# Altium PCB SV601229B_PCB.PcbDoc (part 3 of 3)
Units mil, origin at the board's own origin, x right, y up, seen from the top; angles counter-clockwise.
Board outline 3875 x 2375 mil, 10 copper layers (Top Layer, MidLayer1, MidLayer2, MidLayer3, MidLayer4, MidLayer5, MidLayer6, MidLayer7, MidLayer8, Bottom Layer), stack 98 mil thick; 184 components, 75 nets, 694 pads, 496 vias.
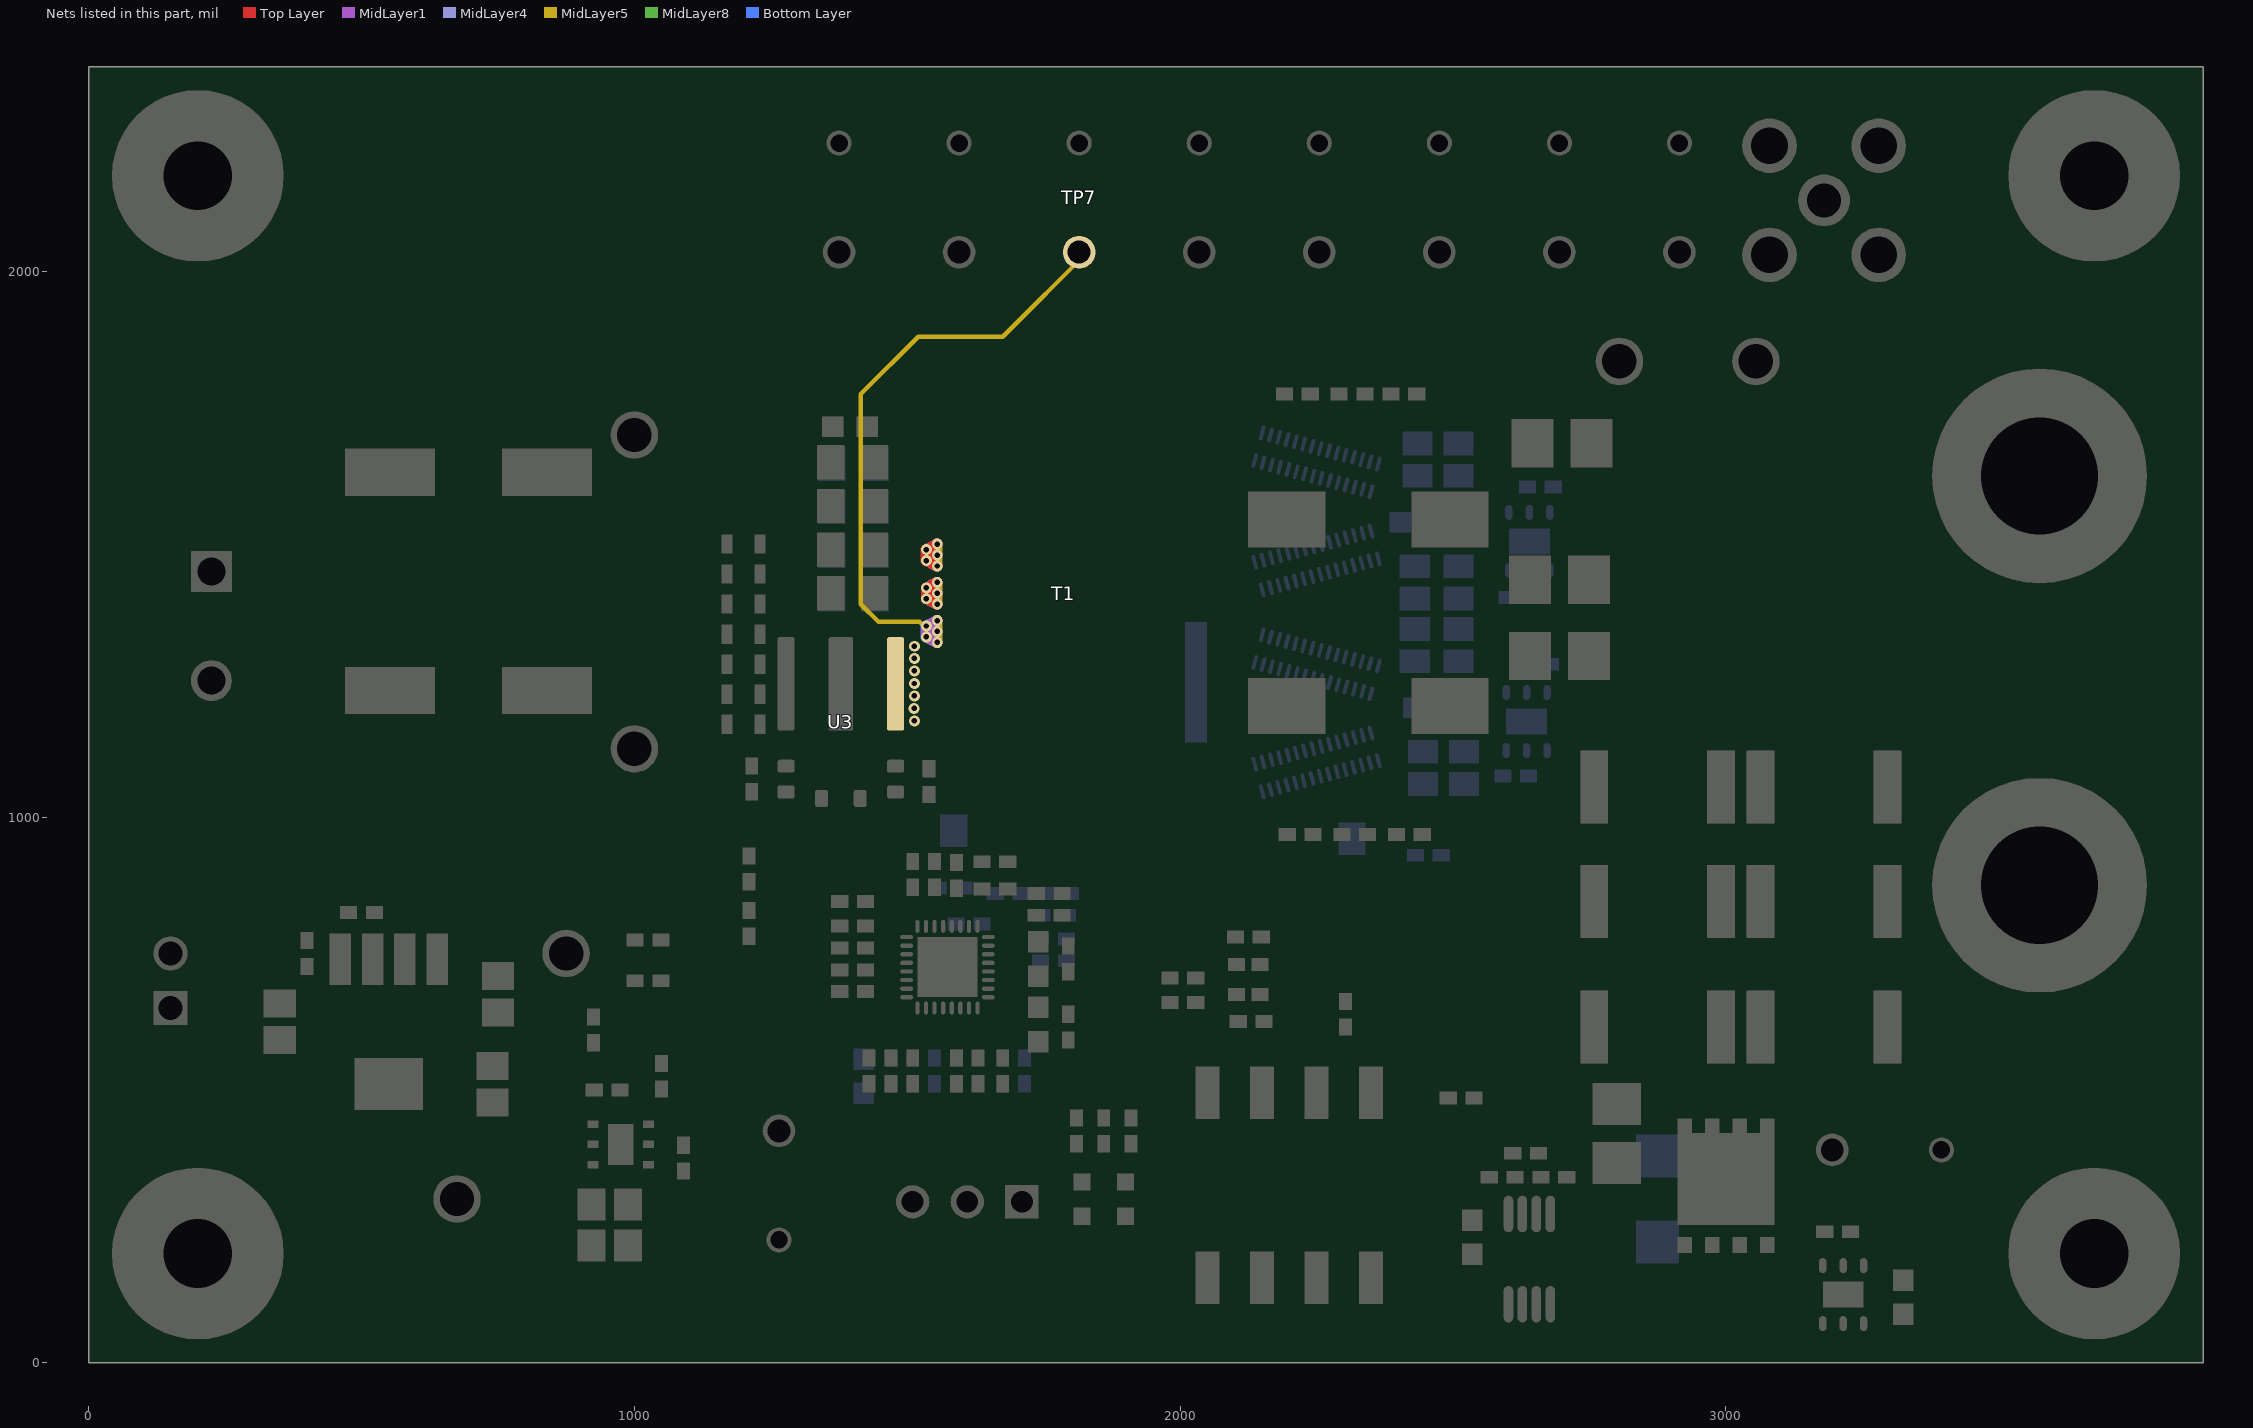
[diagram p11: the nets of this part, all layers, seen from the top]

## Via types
v1: diameter 20, hole 10, Top Layer to Bottom Layer, tented both sides, 459 vias
v2: diameter 20, hole 10, Top Layer to Bottom Layer, 29 vias
v3: diameter 19.68, hole 7.87, Top Layer to Bottom Layer, 8 vias

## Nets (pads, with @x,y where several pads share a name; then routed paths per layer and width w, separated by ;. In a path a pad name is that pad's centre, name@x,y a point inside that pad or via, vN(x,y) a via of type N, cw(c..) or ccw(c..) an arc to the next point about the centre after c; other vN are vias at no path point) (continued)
VPRI_SW: T1.1 TP7.1 U3.8 | length 4010.5
  Top Layer w20: v1@1554.64,1460 1546.64,1464 v1@1534.64,1470 ; v1@1554.64,1480 1546.64,1476 1542.64,1474 v1@1534.64,1470 ; v1@1554.64,1500 1546.64,1496 1534.64,1490 v1@1534.64,1470 ; v1(1555,1390) 1547,1394 v1(1535,1400) ; v1(1555,1410) 1547,1406 1543,1404 v1(1535,1400) ; v1(1555,1430) 1547,1426 v1(1535,1420) v1(1535,1400)
  MidLayer1 w20: v1(1555,1320) 1547,1324 v1(1535,1330) ; v1(1555,1340) 1547,1336 1543,1334 v1(1535,1330) ; v1(1555,1360) 1547,1356 v1(1535,1350) v1(1535,1330) ; v1(1555,1390) 1547,1394 v1(1535,1400) ; v1(1555,1410) 1547,1406 1543,1404 v1(1535,1400) ; v1(1555,1430) 1547,1426 v1(1535,1420) v1(1535,1400) ; v1(1555,1460) 1547,1464 v1(1535,1470) ; v1(1555,1480) 1547,1476 1543,1474 v1(1535,1470) ; v1(1555,1500) 1547,1496 v1(1535,1490) v1(1535,1470)
  MidLayer4 w20: v1(1555,1320) 1547,1324 v1(1535,1330) ; v1(1555,1340) 1547,1336 1543,1334 v1(1535,1330) ; v1(1555,1360) 1547,1356 v1(1535,1350) v1(1535,1330) ; v1(1555,1390) 1547,1394 v1(1535,1400) ; v1(1555,1410) 1547,1406 1543,1404 v1(1535,1400) ; v1(1555,1430) 1547,1426 v1(1535,1420) v1(1535,1400) ; v1(1555,1460) 1547,1464 v1(1535,1470) ; v1(1555,1480) 1547,1476 1543,1474 v1(1535,1470) ; v1(1555,1500) 1547,1496 v1(1535,1490) v1(1535,1470)
  MidLayer5 w8: v1@1530.1,1350 1522.35,1357.75 1447.25,1357.75 1415,1390 1415,1775 1520,1880 1675,1880 TP7.1@1835,2040
  MidLayer5 w20: v1(1535,1330) v1@1543,1334 ; v1(1535,1330) v1(1535,1350) ; v1(1535,1330) v1(1535,1350) ; v1(1535,1330) v1(1535,1350) ; v1(1535,1330) v1(1535,1350) ; v1(1535,1330) v1@1547,1324 ; v1(1535,1330) v1@1547,1324 ; v1(1535,1330) v1@1547,1324 ; v1(1535,1330) v1@1547,1324 ; v1(1535,1330) v1@1543,1334 ; v1(1535,1330) v1@1547,1324 ; v1(1535,1330) v1(1535,1350) ; v1(1535,1350) v1@1543,1346 ; v1(1535,1350) v1@1547,1356 ; v1(1535,1350) v1@1547,1356 ; v1(1535,1350) v1@1547,1356 ; v1(1535,1350) v1@1547,1356 ; v1(1535,1350) v1@1547,1356 ; v1(1535,1350) v1@1543,1346 ; v1(1535,1400) v1(1535,1420) ; v1(1535,1400) v1(1535,1420) ; v1(1535,1400) v1(1535,1420) ; v1(1535,1400) v1(1535,1420) ; v1(1535,1400) v1@1543,1404 ; v1(1535,1400) v1@1547,1394 ; v1(1535,1400) v1@1547,1394 ; v1(1535,1400) v1@1547,1394 ; v1(1535,1400) v1@1543,1404 ; v1(1535,1400) v1@1543,1404 ; v1(1535,1400) v1@1547,1394 ; v1(1535,1400) v1@1547,1394 ; v1(1535,1400) v1(1535,1420) ; v1(1535,1400) v1@1543,1404 ; v1(1535,1400) v1@1547,1394 ; v1(1535,1400) v1(1535,1420) ; v1(1535,1420) v1@1547,1426 ; v1(1535,1420) v1@1547,1426 ; v1(1535,1420) v1@1547,1426 ; v1(1535,1420) v1@1547,1426 ; v1(1535,1420) v1@1547,1426 ; v1(1535,1420) v1@1547,1426 ; v1(1535,1420) 1543,1416 1547,1414 v1(1555,1410) ; v1(1535,1470) v1@1547,1464 ; v1(1535,1470) v1@1543,1474 ; v1(1535,1470) v1@1543,1474 ; v1(1535,1470) v1(1535,1490) ; v1(1535,1470) v1(1535,1490) ; v1(1535,1470) v1(1535,1490) ; v1(1535,1470) v1@1543,1474 ; v1(1535,1470) v1@1543,1474 ; v1(1535,1470) v1@1543,1474 ; v1(1535,1470) v1(1535,1490) ; v1(1535,1470) v1(1535,1490) ; v1(1535,1470) v1(1535,1490) ; v1(1535,1470) v1@1547,1464 ; v1(1535,1470) v1@1547,1464 ; v1(1535,1470) v1@1547,1464 ; v1(1535,1470) v1@1547,1464 ; v1(1535,1470) v1@1547,1464 ; v1(1535,1470) v1@1543,1474 ; v1(1535,1470) v1@1547,1464 ; v1(1535,1470) v1(1535,1490) ; v1(1535,1490) v1@1547,1496 ; v1(1535,1490) v1@1547,1496 ; v1(1535,1490) v1@1547,1496 ; v1(1535,1490) v1@1547,1496 ; v1(1535,1490) v1@1547,1496 ; v1(1535,1490) v1@1547,1496 ; v1(1535,1490) v1@1547,1496 ; v1(1535,1490) 1543,1486 1547,1484 v1(1555,1480) ; v1@1543,1334 v1@1547,1336 ; v1@1543,1334 v1@1547,1336 ; v1@1543,1346 v1@1547,1344 ; v1@1543,1346 v1@1547,1344 ; v1@1543,1404 v1@1547,1406 ; v1@1543,1404 v1@1547,1406 ; v1@1543,1404 v1@1547,1406 ; v1@1543,1404 v1@1547,1406 ; v1@1543,1474 v1@1547,1476 ; v1@1543,1474 v1@1547,1476 ; v1@1543,1474 v1@1547,1476 ; v1@1543,1474 v1@1547,1476 ; v1@1543,1474 v1@1547,1476 ; v1@1543,1474 v1@1547,1476 ; v1@1547,1324 v1(1555,1320) ; v1@1547,1324 v1(1555,1320) ; v1@1547,1324 v1(1555,1320) ; v1@1547,1324 v1(1555,1320) ; v1@1547,1336 v1(1555,1340) ; v1@1547,1336 v1(1555,1340) ; v1@1547,1344 v1(1555,1340) ; v1@1547,1344 v1(1555,1340) ; v1@1547,1356 v1(1555,1360) ; v1@1547,1356 v1(1555,1360) ; v1@1547,1356 v1(1555,1360) ; v1@1547,1356 v1(1555,1360) ; v1@1547,1356 v1(1555,1360) ; v1@1547,1394 v1(1555,1390) ; v1@1547,1394 v1(1555,1390) ; v1@1547,1394 v1(1555,1390) ; v1@1547,1394 v1(1555,1390) ; v1@1547,1394 v1(1555,1390) ; v1@1547,1394 v1(1555,1390) ; v1@1547,1406 v1(1555,1410) ; v1@1547,1406 v1(1555,1410) ; v1@1547,1406 v1(1555,1410) ; v1@1547,1406 v1(1555,1410) ; v1@1547,1426 v1(1555,1430) ; v1@1547,1426 v1(1555,1430) ; v1@1547,1426 v1(1555,1430) ; v1@1547,1426 v1(1555,1430) ; v1@1547,1426 v1(1555,1430) ; v1@1547,1426 v1(1555,1430) ; v1@1547,1464 v1(1555,1460) ; v1@1547,1464 v1(1555,1460) ; v1@1547,1464 v1(1555,1460) ; v1@1547,1464 v1(1555,1460) ; v1@1547,1464 v1(1555,1460) ; v1@1547,1464 v1(1555,1460) ; v1@1547,1464 v1(1555,1460) ; v1@1547,1476 v1(1555,1480) ; v1@1547,1476 v1(1555,1480) ; v1@1547,1476 v1(1555,1480) ; v1@1547,1476 v1(1555,1480) ; v1@1547,1476 v1(1555,1480) ; v1@1547,1476 v1(1555,1480) ; v1@1547,1496 v1(1555,1500) ; v1@1547,1496 v1(1555,1500) ; v1@1547,1496 v1(1555,1500) ; v1@1547,1496 v1(1555,1500) ; v1@1547,1496 v1(1555,1500) ; v1@1547,1496 v1(1555,1500) ; v1@1547,1496 v1(1555,1500) ; v1(1555,1320) v1(1555,1340) ; v1(1555,1320) v1(1555,1340) ; v1(1555,1340) v1(1555,1360) ; v1(1555,1340) v1(1555,1360) ; v1(1555,1390) v1(1555,1410) ; v1(1555,1390) v1(1555,1410) ; v1(1555,1410) v1(1555,1430) ; v1(1555,1410) v1(1555,1430) ; v1(1555,1460) v1(1555,1480) ; v1(1555,1460) v1(1555,1480) ; v1(1555,1480) v1(1555,1500) ; v1(1555,1480) v1(1555,1500)
  MidLayer8 w20: v1(1555,1320) 1547,1324 v1(1535,1330) ; v1(1555,1340) 1547,1336 1543,1334 v1(1535,1330) ; v1(1555,1360) 1547,1356 v1(1535,1350) v1(1535,1330) ; v1(1555,1390) 1547,1394 v1(1535,1400) ; v1(1555,1410) 1547,1406 1543,1404 v1(1535,1400) ; v1(1555,1430) 1547,1426 v1(1535,1420) v1(1535,1400) ; v1(1555,1460) 1547,1464 v1(1535,1470) ; v1(1555,1480) 1547,1476 1543,1474 v1(1535,1470) ; v1(1555,1500) 1547,1496 v1(1535,1490) v1(1535,1470)
  Bottom Layer w20: v1@1543,1403 v1@1547,1405 ; v1@1547,1405.96 v1(1555,1410) ; v1@1554,1319.82 1546,1323.82 v1@1534,1329.82 ; v1@1554,1339.82 1546,1335.82 1542,1333.82 v1@1534,1329.82 ; v1@1554,1359.82 1546,1355.82 1534,1349.82 v1@1534,1329.82 ; v1(1555,1390) 1547,1393.96 v1(1535,1400) v1(1535,1420) 1547,1425.96 v1(1555,1430) ; v1(1555,1460) 1547,1464 v1(1535,1470) ; v1(1555,1480) 1547,1476 1543,1474 v1(1535,1470) ; v1(1555,1500) 1547,1496 v1(1535,1490) v1(1535,1470)
  other v1: 1513,1176 1512.73,1199 1513,1222 1513,1244.68 1513,1267.76 1513,1290.73 1513,1313
pads on no net: H1.1 H2.1 H3.1 H4.1 LBL1.0 Q2. Q3. Q4. Q5. U1.2 U2.5 U3.1A U3.1B U3.1C U3.1D U3.1E U3.8A U3.8B U3.8C U3.8D U3.8E U3.9A U3.9B U3.9C U3.9D U3.9E U4.4 U4.22 U4.30 U4.32 U5.5

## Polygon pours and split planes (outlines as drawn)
VPRI_SW on Top Layer "VPRI_SW_L01_P182" (solid, remove dead copper, pour order 182): 44 vertices, not listed, extent 1535,1050.26 2132.4,1722.27
VPRI_SW on Top Layer "VPRI_SW_L01_P180" (solid, remove dead copper, pour order 180): 1541.07,1306.07 1565.54,1306.07 1565.54,1370.42 1566.22,1371.1 1505.41,1371.1 1494.1,1359.79 1462.47,1359.79 1462.47,1320.61 1463.62,1319.45 1463.62,1157.89 1515.47,1157.89 1525.73,1168.15 1525.73,1290.73
VOUT on Top Layer "Top Layer-No Net 14" (solid, remove dead copper, pour order 155): 2890,1755 3140,1755 3300,1915 3705,1915 3850,1770 3850,1360 3625,1135 2725,1135 2710,1120 2710,1045 2695,1030 2520,1030 2400,1150 2400,1585 2570,1755
SEC_D1 on Top Layer "Top Layer-No Net 16" (solid, remove dead copper, pour order 142): 2015,1395 2095,1395 2150,1450 2310,1450 2350,1490 2350,1560 2340,1570 2255,1570 2210,1615 2015,1615 2010,1610 2010,1400 2015,1395
SPGND on Top Layer "Top Layer-No Net 13" (solid, remove dead copper, pour order 132): 2850,25 3020,25 3055,60 3055,225 3045,235 2910,235 2860,285 2860,390 2840,410 2730,410 2675,355 2675,200
DR4 on Top Layer "Top Layer-No Net 12" (solid, remove dead copper, pour order 131): 3185,725 3310,725 3350,685 3350,495 3105,250 2910,250 2900,260 2900,440 3002.5,542.5 3162.5,542.5 3170,550 3170,710
V3P3_CTRL on Top Layer "Top Layer-No Net 10" (solid, remove dead copper, pour order 108): 930,220 945,220 960,235 960,345 930,375 880,375 865,360 865,235 880,220
V5_CTRL on Top Layer "Top Layer-No Net 8" (solid, remove dead copper, pour order 106): 905,600 1055,600 1090,565 1090,430 1060,400 920,400 885,435 885,580 905,600
V5 on Top Layer "Top Layer-No Net 7" (solid, remove dead copper, pour order 94): 885,610 955,610 1025,680 1025,835 970,890 875,890 830,845 830,645 865,610
VBIAS_IN on Top Layer "Top Layer-No Net 5" (solid, remove dead copper, pour order 91): 80,940 730,940 810,860 810,700 790,680 450,680 400,630 300,630 220,710 70,710 20,760 20,880
VPRI_CAP on Top Layer "Top Layer-No Net" (solid, remove dead copper, pour order 121): 1495,1375 1505,1385 1505,1715 1485,1735 1435,1735 1405,1705 1405,1385 1415,1375
VBUS_P on Top Layer "Top Layer-No Net 3" (solid, remove dead copper, pour order 125): 1230,1135 1270,1135 1295,1160 1295,1345 1325,1375 1385,1375 1390,1380 1390,1735 1385,1740 1270,1740 1220,1690 1220,1145
VBUS_N on Top Layer "Top Layer-No Net 1" (solid, remove dead copper, pour order 124): 1425,1160 1425,1330 1415,1340 1345,1340 1335,1330 1335,1165 1345,1155 1420,1155 1425,1160
VOUT on Top Layer "Top Layer-No Net 4" (solid, remove dead copper, pour order 126): 2430,1645 2430,1125 2470,1085 2550,1085 2575,1110 2575,1630 2555,1650 2450,1650 2430,1630
VBUS_N on Top Layer "Top Layer-No Net 2" (solid, remove dead copper, pour order 127): 1160,1520 1180,1520 1185,1515 1185,1145 1175,1135 1135,1135 1130,1140 1130,1510 1140,1520
VBUS_P on Top Layer "Top Layer-No Net 9" (solid, remove dead copper, pour order 97): 105,1750 1375,1750 1385,1740 1385,1565 1335,1515 1230,1515 1205,1540 1125,1540 1095,1510 1095,1290 855,1050 480,1050 50,1480 50,1695
SEC_D2 on Top Layer "Top Layer-No Net 15" (solid, remove dead copper, pour order 137): 2035,1105 2050,1090 2080,1090 2195,1090 2275,1170 2350,1170 2360,1180 2360,1235 2340,1255 2200,1255 2100,1355 2035,1355
VOUT on Top Layer "Top Layer-No Net 17" (solid, remove dead copper, pour order 156): 2605,425 2835,425 2870,460 2870,705 2855,720 2725,720 2705,740 2705,860 2685,880 2550,880 2520,850 2520,645 2590,575 2590,440 2605,425
SPGND on Top Layer "Top Layer-No Net 18" (solid, remove dead copper, pour order 163): 2715,1635 2815,1635 2835,1655 2835,1715 2820,1730 2715,1730
SPGND on Top Layer "Top Layer-No Net 19" (solid, remove dead copper, pour order 165): 2710,1390 2815,1390 2830,1405 2830,1465 2810,1485 2710,1485
SPGND on Top Layer "Top Layer-No Net 19" (solid, remove dead copper, pour order 164): 2710,1250 2815,1250 2830,1265 2830,1325 2810,1345 2710,1345
SPGND on Top Layer "Top Layer-No Net 20" (solid, remove dead copper, pour order 166): 2715,1250 2815,1250 2830,1265 2830,1325 2810,1345 2710,1345 2710,1250
AGND on Top Layer "Top Layer-No Net 21" (solid, remove dead copper, pour order 178): 23 vertices, not listed, extent 31.54,0 2646.54,970
SEC_D1 on MidLayer1 "SEC_D1_L02_P209" (solid, remove dead copper, pour order 209): 26 vertices, not listed, extent 1538,1063.19 2097,1692
SEC_D2 on MidLayer1 "Top Layer-No Net 15" (solid, remove dead copper, pour order 195): 2041,1099 2050,1090 2080,1090 2195,1090 2230,1125 2320,1125 2360,1165 2360,1235 2340,1255 2200,1255 2100,1355 2041,1355
SEC_D1 on MidLayer1 "Top Layer-No Net 16" (solid, remove dead copper, pour order 193): 2015,1395 2095,1395 2150,1450 2310,1450 2350,1490 2350,1560 2340,1570 2295,1615 2015,1615 2010,1610 2010,1400
AGND on MidLayer1 "MidLayer1-No Net" (solid, remove dead copper, pour order 90): 80,940 2520,940 2605,855 2605,515 2740,380 3350,380 3440,290 3440,80 3380,20 80,20 20,80 20,880
VBUS_N on MidLayer1 "MidLayer1-No Net 1" (solid, remove dead copper, pour order 103): 95,1050 1090,1050 1185,1145 1410,1145 1425,1160 1425,1705 1380,1750 106.45,1750 50,1693.55 50,1095 95,1050
VOUT on MidLayer1 "Top Layer-No Net 14" (solid, remove dead copper, pour order 154): 2890,1755 3140,1755 3300,1915 3705,1915 3850,1770 3850,1360 3625,1135 3420,1135 3315,1030 2520,1030 2400,1150 2400,1585 2570,1755
VOUT on MidLayer1 "MidLayer1-No Net 2" (solid, remove dead copper, pour order 173): 2600,1045 2650,995 2650,530 2760,420 3130,420 3270,420 3360,510 3360,1140 3310,1190 2710,1190 2600,1080
VPRI_SW on Bottom Layer "VPRI_SW_L10_P223" (solid, remove dead copper, pour order 223): 1540.66,1305.97 1565.13,1305.97 1565.13,1370.32 1565.81,1371 1505,1371 1493.69,1359.69 1462.06,1359.69 1462.06,1320.5 1463.21,1319.35 1463.21,1157.79 1515.06,1157.79 1525.32,1168.05 1525.32,1290.62
SEC_D1 on Bottom Layer "SEC_D1_L10_P219" (solid, remove dead copper, pour order 219): 26 vertices, not listed, extent 1537.96,1063.4 2096.96,1692.21
SPGND on Bottom Layer "Bottom Layer-No Net 15" (solid, pour order 147): 2400,1085 2400,1105 2390,1115 2375,1115 2365,1105 2365,1095 2375,1085
VOUT on Bottom Layer "Bottom Layer-No Net 14" (solid, remove dead copper, pour order 146): 2565,1240 2565,1285 2550,1300 2405,1300 2400,1295 2400,1250 2415,1235 2560,1235
VOUT on Bottom Layer "Bottom Layer-No Net 13" (solid, remove dead copper, pour order 145): 2550,1575 2560,1585 2560,1590 2560,1630 2545,1645 2410,1645 2400,1635 2400,1585 2410,1575
VOUT on Bottom Layer "Bottom Layer-No Net 12" (solid, remove dead copper, pour order 144): 2545,1440 2560,1455 2560,1485 2560,1500 2550,1510 2410,1510 2400,1500 2400,1450 2410,1440
SPGND on Bottom Layer "Bottom Layer-No Net 4" (solid, remove dead copper, pour order 105): 2135,1025 2200,1090 2420,1090 2435,1075 2435,1010 2410,985 2150,985 2135,1000
SEC_D2 on Bottom Layer "Bottom Layer-No Net" (solid, remove dead copper, pour order 100): 2044.31,1355 2120,1279.31 2245.69,1279.31 2285,1240 2332.28,1240 2362.28,1210 2362.28,1156.41 2330.87,1125 2297.46,1125 2272.46,1100 2044.31,1100
VBUS_N on Bottom Layer "Bottom Layer-No Net 3" (solid, remove dead copper, pour order 123): 1145,1135 1400,1135 1425,1160 1425,1320 1405,1340 1405,1675 1400,1680 1275,1680 1130,1535 1130,1150
VPRI_CAP on Bottom Layer "Bottom Layer-No Net 2" (solid, remove dead copper, pour order 122): 1492.75,1680 1494.04,1681.3 1511.36,1681.3 1510,1512.73 1510,1385 1500,1375 1415,1375 1410,1380 1410,1675 1415,1680
VBUS_N on Bottom Layer "MidLayer1-No Net 1" (solid, remove dead copper, pour order 102): 95,1050 1090,1050 1185,1145 1410,1145 1425,1160 1425,1705 1380,1750 106.45,1750 50,1693.55 50,1095 95,1050
SPGND on Bottom Layer "Bottom Layer-No Net 6" (solid, remove dead copper, pour order 93): 2415,1090 2550,1090 2560,1080 2560,1005 2540,985 2405,985 2400,990 2400,1075 2415,1090
VOUT on Bottom Layer "Bottom Layer-No Net 7" (solid, remove dead copper, pour order 96): 2450,1100 2550,1100 2560,1110 2560,1165 2555,1170 2550,1175 2420,1175 2405,1160 2405,1115 2420,1100
SPGND on Bottom Layer "Bottom Layer-No Net 8" (solid, remove dead copper, pour order 99): 25 vertices, not listed, extent 2115,1270 2555,1480
SEC_D1 on Bottom Layer "Bottom Layer-No Net 9" (solid, remove dead copper, pour order 101): 18 vertices, not listed, extent 2015,1395 2365,1675
SPGND on Bottom Layer "Bottom Layer-No Net 10" (solid, remove dead copper, pour order 104): 2145,1700 2170,1675 2240,1675 2245,1675 2280,1640 2365,1640 2385,1660 2385,1725 2360,1750 2275,1750 2140,1750 2130,1740 2130,1715 2145,1700
SPGND on Bottom Layer "Bottom Layer-No Net 11" (solid, remove dead copper, pour order 107): 2370,1665 2380,1655 2550,1655 2560,1665 2560,1740 2550,1750 2360,1750 2350,1740 2350,1685
DR4 on Bottom Layer "Bottom Layer-No Net 5" (solid, remove dead copper, pour order 157): 3185,725 3310,725 3350,685 3350,525 3115,290 2870,290 2830,330 2830,435 2930,535 3165,535 3180,550 3180,720 3185,725
SPGND on Bottom Layer "Bottom Layer-No Net 16" (solid, remove dead copper, pour order 158): 2805,90 3045,90 3075,120 3075,240 3045,270 2820,270 2785,235 2785,110 2805,90
VOUT on Bottom Layer "Bottom Layer-No Net 17" (solid, remove dead copper, pour order 159): 2670,475 2825,475 2870,520 2870,705 2855,720 2610,720 2585,695 2585,500 2610,475
SPGND on Bottom Layer "Bottom Layer-No Net 18" (solid, remove dead copper, pour order 160): 41 vertices, not listed, extent 2480,590 3850,1920
PGND on Bottom Layer "Bottom Layer-No Net 19" (solid, remove dead copper, pour order 168): 1610,1000 1610,1080 1580,1110 1505,1110 1500,1105 1500,1075 1505,1070 1550,1070 1560,1060 1560,1000
AGND on Bottom Layer "Bottom Layer-No Net 20" (solid, remove dead copper, pour order 169): 18 vertices, not listed, extent 20,25 2755,955
SEC_D1 on MidLayer6 "SEC_D1_L07_P215" (solid, remove dead copper, pour order 215): 26 vertices, not listed, extent 1538,1063.19 2097,1692
SEC_D1 on MidLayer6 "Top Layer-No Net 16" (solid, remove dead copper, pour order 141): 2015,1395 2095,1395 2150,1450 2310,1450 2350,1490 2350,1560 2340,1570 2295,1615 2015,1615 2010,1610 2010,1400
SEC_D2 on MidLayer6 "Top Layer-No Net 15" (solid, remove dead copper, pour order 136): 2043,1097 2050,1090 2080,1090 2195,1090 2230,1125 2320,1125 2360,1165 2360,1235 2340,1255 2200,1255 2096,1359 2043,1359
SPGND on MidLayer6 "MidLayer4-No Net 2" (solid, remove dead copper, pour order 152): 41 vertices, not listed, extent 2100,25 3850,1880
AGND on MidLayer6 "MidLayer6-No Net" (solid, remove dead copper, pour order 177): 105,940 2545,940 2670,815 2670,180 2515,25 80,25 20,85 20,880 80,940
VPRI_SW on MidLayer4 "VPRI_SW_L05_P186" (solid, remove dead copper, pour order 186): 28 vertices, not listed, extent 1535,1064.41 2103.35,1696.3
SEC_D1 on MidLayer4 "Top Layer-No Net 16" (solid, remove dead copper, pour order 140): 2015,1395 2095,1395 2150,1450 2310,1450 2350,1490 2350,1560 2340,1570 2295,1615 2015,1615 2010,1610 2010,1400
SEC_D2 on MidLayer4 "Top Layer-No Net 15" (solid, remove dead copper, pour order 135): 2035,1105 2050,1090 2080,1090 2195,1090 2230,1125 2320,1125 2355,1160 2355,1195 2345,1205 2345,1250 2340,1255 2200,1255 2100,1355 2035,1355
VBUS_P on MidLayer4 "Top Layer-No Net 9" (solid, remove dead copper, pour order 95): 105,1750 1375,1750 1385,1740 1385,1565 1335,1515 1230,1515 1205,1540 1125,1540 1095,1510 1095,1340 805,1050 480,1050 50,1480 50,1695 105,1750
SPGND on MidLayer4 "MidLayer4-No Net 2" (solid, remove dead copper, pour order 151): 41 vertices, not listed, extent 2100,25 3850,1880
SEC_D1 on MidLayer3 "SEC_D1_L04_P213" (solid, remove dead copper, pour order 213): 26 vertices, not listed, extent 1538,1063.19 2097,1692
SEC_D2 on MidLayer3 "Top Layer-No Net 15" (solid, remove dead copper, pour order 201): 2040.65,1099 2049.65,1090 2079.65,1090 2194.65,1090 2229.65,1125 2319.65,1125 2359.65,1165 2359.65,1235 2339.65,1255 2199.65,1255 2099.65,1355 2040.65,1355
SEC_D1 on MidLayer3 "Top Layer-No Net 16" (solid, remove dead copper, pour order 139): 2015,1395 2095,1395 2150,1450 2310,1450 2350,1490 2350,1560 2340,1570 2295,1615 2015,1615 2010,1610 2010,1400
CTRL_VREF on MidLayer3 "MidLayer3-No Net 1" (solid, remove dead copper, pour order 133): 1720,430 1840,550 1840,850 1735,955 1445,955 1255,765 1255,615 1440,430
SPGND on MidLayer3 "MidLayer4-No Net 2" (solid, remove dead copper, pour order 150): 41 vertices, not listed, extent 2100,25 3850,1880
V5_LM5200 on MidLayer3 "MidLayer3-No Net" (solid, remove dead copper, pour order 170): 18 vertices, not listed, extent 1035,735 1565,1110
SEC_D1 on MidLayer2 "SEC_D1_L03_P211" (solid, remove dead copper, pour order 211): 26 vertices, not listed, extent 1538,1063.19 2097,1692
SEC_D1 on MidLayer2 "Top Layer-No Net 16" (solid, remove dead copper, pour order 199): 2015,1395 2095,1395 2150,1450 2310,1450 2350,1490 2350,1560 2340,1570 2295,1615 2015,1615 2010,1610 2010,1400
SEC_D2 on MidLayer2 "Top Layer-No Net 15" (solid, remove dead copper, pour order 197): 2041,1099 2050,1090 2080,1090 2195,1090 2230,1125 2320,1125 2360,1165 2360,1235 2340,1255 2200,1255 2100,1355 2041,1355
V5_CTRL on MidLayer2 "MidLayer2-No Net 2" (solid, remove dead copper, pour order 111): 905,610 1135,610 1455,930 1540,930 1615,855 2585,855 2695,745 2695,610 2635,550 2020,550 1830,360 1050,360 875,535 875,580
V5 on MidLayer2 "MidLayer2-No Net" (solid, remove dead copper, pour order 92): 500,940 815,940 860,895 860,520 1035,345 1855,345 2035,525 3315,525 3440,400 3440,80 3380,20 590,20 360,250 360,800
V5_GD on MidLayer2 "MidLayer2-No Net 1" (solid, remove dead copper, pour order 167): 21 vertices, not listed, extent 1000,620 2700,1575
SEC_D1 on MidLayer5 "SEC_D1_L06_P221" (solid, remove dead copper, pour order 221): 26 vertices, not listed, extent 1537.96,1063.4 2096.96,1692.21
SEC_D1 on MidLayer5 "Top Layer-No Net 16" (solid, remove dead copper, pour order 203): 2015,1395 2095,1395 2150,1450 2310,1450 2350,1490 2350,1560 2340,1570 2295,1615 2015,1615 2010,1610 2010,1400
SEC_D2 on MidLayer5 "Top Layer-No Net 15" (solid, remove dead copper, pour order 134): 2041,1099 2050,1090 2080,1090 2195,1090 2230,1125 2320,1125 2360,1165 2360,1235 2340,1255 2200,1255 2100,1355 2041,1355
VBUS_N on MidLayer5 "MidLayer1-No Net 1" (solid, remove dead copper, pour order 98): 95,1050 1090,1050 1185,1145 1410,1145 1425,1160 1425,1705 1380,1750 106.45,1750 50,1693.55 50,1095 95,1050
VOUT on MidLayer5 "Top Layer-No Net 14" (solid, remove dead copper, pour order 153): 2890,1755 3140,1755 3300,1915 3705,1915 3850,1770 3850,1360 3625,1135 3420,1135 3315,1030 2520,1030 2400,1150 2400,1585 2570,1755
VOUT on MidLayer5 "MidLayer5-No Net" (solid, remove dead copper, pour order 172): 2510,1090 2510,630 2645,495 2870,495 2895,520 3035,520 3315,800 3315,1090 3265,1140 2560,1140
SEC_D1 on MidLayer7 "SEC_D1_L08_P217" (solid, remove dead copper, pour order 217): 26 vertices, not listed, extent 1538,1063.19 2097,1692
SEC_D2 on MidLayer7 "Top Layer-No Net 15" (solid, remove dead copper, pour order 207): 2044,1096 2050,1090 2080,1090 2195,1090 2230,1125 2320,1125 2360,1165 2360,1235 2340,1255 2200,1255 2096,1359 2044,1359
SEC_D1 on MidLayer7 "Top Layer-No Net 16" (solid, remove dead copper, pour order 205): 2015,1395 2095,1395 2150,1450 2310,1450 2350,1490 2350,1560 2340,1570 2295,1615 2015,1615 2010,1610 2010,1400
V3P3_CTRL on MidLayer7 "MidLayer7-No Net" (solid, remove dead copper, pour order 138): 1020,20 2135,20 2190,75 2190,535 1855,870 1275,870 835,430 835,190 1005,20
PGND on MidLayer7 "MidLayer7-No Net 1" (solid, remove dead copper, pour order 171): 1315,2300 1800,2300 1870,2230 1870,1940 1730,1800 1485,1800 1390,1705 1390,1240 1530,1100 1530,1005 1470,945 820,945 720,1045 720,1925 1095,2300
SPGND on MidLayer7 "MidLayer7-No Net 2" (solid, remove dead copper, pour order 174): 2150,955 2505,955 2560,1010 2560,1065 2540,1085 2160,1085 2125,1050 2125,980
SPGND on MidLayer7 "MidLayer7-No Net 3" (solid, remove dead copper, pour order 175): 2250,1280 2320,1280 2360,1320 2385,1320 2420,1285 2550,1285 2570,1305 2570,1415 2530,1455 2335,1455 2315,1435 2155,1435 2120,1400 2120,1360 2200,1280
SPGND on MidLayer7 "MidLayer7-No Net 4" (solid, remove dead copper, pour order 176): 2145,1635 2330,1635 2380,1685 2525,1685 2540,1700 2540,1740 2520,1760 2130,1760 2100,1730 2100,1680
VPRI_SW on MidLayer8 "VPRI_SW_L09_P191" (solid, remove dead copper, pour order 191): 32 vertices, not listed, extent 1547,1060 2093,1687.52
SPGND on MidLayer8 "MidLayer4-No Net" (solid, remove dead copper, pour order 148): 2370,1085 2585,1085 2670,1170 2670,1195 2580,1285 2450,1285 2415,1320 2370,1320 2350,1300 2350,1220 2350,1215 2365,1200 2365,1090 2370,1085
SPGND on MidLayer8 "MidLayer4-No Net 1" (solid, remove dead copper, pour order 149): 2380,1460 2640,1460 2680,1500 2680,1535 2535,1680 2375,1680 2350,1655 2350,1575 2365,1560 2365,1475 2380,1460
VPRI_CAP on MidLayer8 "MidLayer8-No Net 1" (solid, remove dead copper, pour order 143): 1524,1524 1495,1495 1485,1495 1480,1500 1480,1540 1480,1635 1490,1645 1505,1645 1524,1626
VPRI_CAP on MidLayer8 "MidLayer8-No Net 2" (solid, remove dead copper, pour order 120): 1485,1375 1500,1375 1515,1390 1515,1670 1505,1680 1460,1680 1455,1675 1455,1385 1465,1375
VBUS_P on MidLayer8 "MidLayer8-No Net" (solid, remove dead copper, pour order 110): 105,1750 1379.31,1750 1406.81,1722.5 1406.81,1381.81 1395,1370 1125,1370 805,1050 95,1050 50,1095 50,1695 50.49,1695.49
SPGND on MidLayer8 "MidLayer8-No Net 3" (solid, remove dead copper, pour order 161): 44 vertices, not listed, extent 2105,390 3845,1915
SPGND on MidLayer8 "MidLayer8-No Net 4" (solid, remove dead copper, pour order 162): 3465,1910 3465,2180 3310,2335 2035,2335 1930,2230 1930,1950 2115,1765 2635,1765 2765,1895 2780,1895 3450,1895

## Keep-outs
Keep-Out Layer:
  the board outline again, w10
  text ".Layer_Name" at 577,-858.49 h60

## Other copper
Top Layer:
  rectangle net SPGND: 3275,130 3345,175
  rectangle net V5: 3250,55 3285,85
  rectangle net V5: 3275,55 3345,110
  rectangle net AGND: 955,465 1000,515
  rectangle net AGND: 701.9,425 778.1,505
  rectangle net AGND: 465,440 620,560
  rectangle net AGND: 305,535 390,620
  rectangle net V5: 700,520 780,600
  rectangle net V5: 500,780 510,800
  rectangle net V5: 510,740 540,840
  rectangle net SEC_D2: 2124.76,1245 2255,1265
  rectangle net SEC_D1: 2125,1480 2255,1505
  rectangle net VBUS_N: 755,1185 925,1305
  rectangle net VBUS_N: 755,1560 925,1675
  rectangle net NetR34_1: 2890,955 3165,1125
  rectangle net NetR35_2: 2890,550 3020,945
  rectangle net NetR34_2: 2725,735 2880,1125
  rectangle net NetR37_1: 3175,735 3350,1125
  rectangle net NetR38_1: 3030,550 3165,945
  rectangle net AGND: 695,615 810,670
  rectangle net V3P3_CTRL: 875,210 940,345
  rectangle net AGND: 965,175 1045,335
  text ".Layer_Name" at 577,-858.49 h60
MidLayer8:
  rectangle net VPRI_CAP: 1474,1375 1510,1615
  rectangle net VPRI_CAP: 1475.65,1615 1510,1650
Bottom Layer:
  rectangle net NetR46_2: 2890,550 3020,945
  rectangle net NetR43_1: 3030,550 3165,945
  rectangle net NetR42_1: 3175,735 3350,1125
  rectangle net NetR42_2: 2890,955 3165,1125
  rectangle net NetR45_2: 2725,735 2880,1125
  rectangle net PGND: 1560,995 1600,1020
  rectangle net PGND: 1525,1070 1565,1110
  rectangle net AGND: 1550,930 1625,955
  rectangle net AGND: 2275,920 2355,955
  text ".Layer_Name" at 577,-858.49 h60

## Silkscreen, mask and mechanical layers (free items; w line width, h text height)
Top Overlay:
  rectangle: 1945,120 2000,175
  rectangle: 1065,50 1395,175
  lines w4: 1708.52,888.6 1730,915 ; 1715,395 1720,390 1770,390 1775,395 ; 1715,925 1730,945 ; 1750,390 1780,360 1895,360 1900,355 ; 1815,360 1820,360 1825,355 ; 2730,310 2730,300 2740,290
  text "V_OUT" at 2845,2000 h40 r90
  text "PWM_H" at 1315,1995 h40 r90
  text "PWM_L" at 1535,1995 h40 r90
  text "SW_NODE" at 1755,1995 h40 r90
  text "SEC_D1" at 1975,1995 h40 r90
  text "SEC_D2" at 2195,1995 h40 r90
  text "SR_G2" at 2415,1995 h40 r90
  text "SR_G1" at 2635,1995 h40 r90
  text "LMG5200 GaN 48V-PoL EVM" at 75,1925 h55
  text "Hot Surface" at 1795,1855 h65
  text "LMG5200POLEVM-10" at 75,1825 h55
  text "Input Volt" at 50,1725 h50
  text "-VOUT+" at 2825,1715 h40
  text "36-75 VDC" at 50,1650 h40
  text "+" at 50,1575 h60
  text "VBUS+" at 925,1575 h40
  text "+" at 3395,1360 h80
  text "Output Voltage" at 3195,1275 h50
  text "0.5-1.5 VDC/50 A" at 3215,1195 h40
  text "-" at 3390,1085 h80
  text "-" at 50,1075 h60
  text "Danger:" at 375,1000 h70
  text "VBUS-" at 925,1000 h40
  text "High Voltage" at 375,900 h70
  text "+" at 50,850 h60
  text "5V" at 750,805 h40
  text "-" at 50,525 h60
  text "Bias Voltage" at 35,475 h40
  text "Idyn" at 3270,445 h40
  text "6V-9V DC" at 50,400 h40
  text "IMON" at 1195,305 h40 r90
  text "AGND" at 585,165 h40
  text "EN" at 1920,135 h40 r90
  text "SCL" at 1535,120 h40 r90
  text "SDA" at 1630,120 h40 r90
  text "GND" at 1735,120 h40 r90
  text "SV601229-'.PCB_Rev'-" at 400,75 h60
  text "EN" at 2050,50 h40
  text "DynLoad" at 2200,50 h40
  text "I2C" at 1565,45 h40
  text "PGOOD" at 1840,30 h40 r90
  text ".Layer_Name" at 577,-858.49 h60
Bottom Overlay:
  text "RoHS Exempt" at 3160,60 h60
  text ".Layer_Name" at 577,-858.49 h60
Top Paste:
  text ".Layer_Name" at 577,-858.49 h60
Bottom Paste:
  text ".Layer_Name" at 577,-858.49 h60
Top Solder:
  text ".Layer_Name" at 577,-858.49 h60
  text ".Layer_Name" at 577,-858.49 h60
Bottom Solder:
  text ".Layer_Name" at 577,-858.49 h60
Drill Guide:
  text ".Layer_Name" at 577,-858.49 h60
M1 Board Outline:
  the board outline again, w10
  text ".Layer_Name" at 577,-858.49 h60
M2 Board Dimensions:
  rectangle: 0,-285.5 125,-160.5
  rectangle: 125,-410.5 500,-285.5
  lines w7: 0,-285.5 1000,-285.5 ; 125,-410.5 125,-160.5 ; 250,-410.5 250,-160.5 ; 500,-410.5 500,-160.5 ; 750,-410.5 750,-160.5 ; 0,-410.5 1000,-410.5 1000,-160.5 0,-160.5 0,-410.5
  text ".Layer_Name" at 577,-858.49 h60
M3 3D STEP Top:
  text ".Layer_Name" at 577,-858.49 h60
M4 3D STEP Bottom:
  text ".Layer_Name" at 577,-858.49 h60
M5 Assembly Top:
  lines w4: 1875,1710 2990,3180
  lines w10: -292,-930.17 6308,-930.17 ; -292,-726.83 6310,-726.83 ; -292,-523.5 -292,-1133.5 3713,-1133.5 6310,-1133.5 6310,-523.5 -291.5,-523.5 -291.5,-1133.5 1284,-1133.5 ; 2173,-1133.5 2173,-523.5 ; 3440,-726.83 3440,-523.5 ; 4280,-726.83 4280,-523.5 ; 4902,-1140 4902,-937.17
  text "Attach 2x ER18 type core halves / using cyano-acrilate glue (super glue)" at 3105,2985 h100
  text "COMPONENTS MARKED 'DNP' SHOULD NOT BE POPULATED." at 1153.5,-318.5 h60
  text "ASSEMBLY VARIANT:" at 1153,-434 h60
  text ".VariantName" at 2189,-434 h60
  text "PCB VIEWED FROM TOP SIDE" at -228.5,-655.67 h60
  text "BOARD #:" at 2248,-655.67 h60
  text ".PRJ_Number" at 2793.5,-655.67 h60
  text "REV:" at 3638,-655.67 h60
  text ".PCB_Rev" at 3929.5,-655.67 h60
  text "SVN REV:" at 4476,-655.67 h60
  text ".VersionControl_RevNumber" at 4982,-655.67 h60
  text "IGNORE ->" at -228.5,-858.49 h60
  text "PLOT NAME =" at -228.5,-1064.34 h60
  text ".plot_File_Name" at 577,-1064.34 h60
  text "GENERATED    :" at 2250,-1064.34 h60
  text ".Print_Date" at 3119.5,-1064.34 h60
  text ".Print_Time" at 3848.5,-1064.34 h60
  text "TEXAS INSTRUMENTS" at 5113,-1064.34 h60
M6 Assembly Bottom:
  lines w10: -292.5,-727.33 6309.5,-727.33 ; -290.5,-930.67 6309.5,-930.67 ; 1115.5,-1140.5 1115.5,-937.67 ; 1737.5,-727.33 1737.5,-524 ; 2577.5,-727.33 2577.5,-524 ; 3844.5,-1134 3844.5,-524 ; 4733.5,-1134 6309,-1134 6309,-524 -292.5,-524 -292.5,-1134 2304.5,-1134 6309.5,-1134 6309.5,-524
  text "COMPONENTS MARKED 'DNP' SHOULD NOT BE POPULATED." at 6102,-318 h60
  text ".VariantName" at 5058,-434 h60
  text "ASSEMBLY VARIANT:" at 6097,-434 h60
  text ".VersionControl_RevNumber" at 1035.5,-656.17 h60
  text "SVN REV:" at 1541.5,-656.17 h60
  text ".PCB_Rev" at 2088,-656.17 h60
  text "REV:" at 2379.5,-656.17 h60
  text ".PRJ_Number" at 3224,-656.17 h60
  text "BOARD #:" at 3769.5,-656.17 h60
  text "PCB VIEWED FROM BOTTOM SIDE" at 6246,-656.17 h60
  text "IGNORE ->" at 2547.85,-858.49 h60
  text "TEXAS INSTRUMENTS" at 904.5,-1064.84 h60
  text ".Print_Time" at 2169,-1064.84 h60
  text ".Print_Date" at 2898,-1064.84 h60
  text "GENERATED    :" at 3767.5,-1064.84 h60
  text ".plot_File_Name" at 5440.5,-1064.84 h60
  text "PLOT NAME =" at 6246,-1064.84 h60
M9 Title Sheet:
  drawing of 57 lines, arcs and shapes, not listed
  text "1" at 739.84,8036.5 h70
  text "2" at 3235.5,8036.5 h70
  text "3" at 5724.84,8036.5 h70
  text "4" at 8231.51,8036.5 h70
  text "5" at 10730.5,8036.5 h70
  text "6" at 13235.5,8036.5 h70
  text "A" at -416.5,6893.5 h70
  text "A" at 14383.5,6893.5 h70
  text "B" at -416.5,4513.5 h70
  text "B" at 14383.5,4513.5 h70
  text "C" at -416.5,2138.5 h70
  text "C" at 14383.5,2138.5 h70
  text "PROJECT TITLE:" at 11343.5,277.5 h45
  text ".PRJ_Title" at 11393.5,144.17 h70
  text "DESIGNED FOR:" at 11343.5,-23.5 h45
  text ".PRJ_Customer" at 11393.5,-163.5 h70
  text "D" at -416.5,-231.5 h70
  text "D" at 14383.5,-231.5 h70
  text "FILE NAME:" at 11343.5,-323.5 h45
  text ".PCB_File_Name_No_Path" at 11393.5,-443.5 h70
  text "Texas Instruments (TI) and/or its licensors do not warrant the accuracy or completeness of this specification" at 6374,-605.34 h45
  text "ENGINEER:" at 11343.5,-613.5 h45
  text "LAYOUT BY:" at 12848.5,-613.5 h45
  text "or any information contained therein. TI and/or its licensors do not warrant that this design will meet" at 6329.01,-718 h45
  text ".PRJ_Engineer" at 11393.5,-768.49 h70
  text ".PCB_Layout" at 12899,-768.49 h70
  text "the specifications, will be suitable for your application or fit for any particular purpose, or will operate in" at 6329.01,-830.67 h45
  text ".Layer_Name" at 577,-858.49 h60
  text "ALTIUM DESIGNER VERSION:" at 12848.5,-923.5 h45
  text "an implementation. TI and/or its licensors do not warrant that the design is production worthy. You should" at 6329.01,-943.33 h45
  text "completely validate and test your design implementation to confirm the system functionality for your application." at 6374,-1056 h45
  text ".print_Scale" at 11393.5,-1056.83 h70
  text ".Application_BuildNumber" at 12899,-1056.83 h70
  text "1" at 739.84,-1263.5 h70
  text "2" at 3235.5,-1263.5 h70
  text "3" at 5724.84,-1263.5 h70
  text "4" at 8231.51,-1263.5 h70
  text "5" at 10730.5,-1263.5 h70
  text "6" at 13235.5,-1263.5 h70
M10 Fab Notes:
  drawing of 188 lines, arcs and shapes, not listed
  text "DESIGN INFORMATION" at 12381.02,5910 h60
  text "MIN. TRACK WIDTH:" at 11736.46,5730 h60
  text "8" at 12832.7,5730 h60
  text "MIL" at 12987.46,5730 h60
  text "MIN. CLEARANCE:" at 11736.46,5598 h60
  text "6.5" at 12772.7,5598 h60
  text "MIL" at 12987.46,5598 h60
  text "MIN. VIA PAD SIZE:" at 11736.46,5466 h60
  text "16" at 12802.71,5466 h60
  text "MIL" at 12987.46,5466 h60
  text "0.05mm (2MIL)" at 12431.46,5324.29 h60
  text "MINIMUM ANNULAR RING" at 11407.23,5320 h60
  text "EXTERNAL" at 13139.46,5320 h60
  text "PER" at 11607.23,5202 h60
  text "IPC-D-275 CLASS 2 LEVEL C" at 11827.23,5202 h60
  text "MIL, HOLES" at 13315.46,5089.71 h60
  text "+/-" at 12923,5089 h60
  text "+/-" at 13777,5089 h60
  text "REGISTRATION TOLERANCES:" at 11407.23,5084 h60
  text "METAL" at 12607,5084 h60
  text "5" at 13183.2,5084 h60
  text "3" at 14016.2,5084 h60
  text "MIL" at 14132.46,5084 h60
  text "MATERIAL:" at 11332.46,4874.54 h60
  text "FR-4 High Tg" at 12318.9,4734.21 h60
  text "FR-408" at 11753.46,4725.64 h60
  text "X" at 12165.46,4725.64 h60
  text "OTHER" at 13241.46,4725.64 h60
  text "62 MIL (1.6mm) +/-10%" at 12073.56,4562.92 h60
  text "93 MIL" at 13707.71,4561 h60
  text "THICKNESS:" at 11407.23,4558.64 h60
  text "OTHER" at 13358.46,4558.64 h60
  text "X" at 13235,4555 h60
  text "TOLERANCE:" at 11407.23,4400.64 h60
  text "X" at 12246.53,4400.64 h60
  text "ANSI IPC-6012 TYPE 3 CLASS 2" at 12433.48,4400.64 h60
  text "OTHER +/-" at 12433.46,4244.64 h60
  text "BOW & TWIST:" at 11407.23,4087.64 h60
  text "X" at 12246.53,4087.64 h60
  text "ANSI IPC-6012 TYPE 3 CLASS 2" at 12433.48,4087.64 h60
  text "OTHER +/-" at 12433.46,3929.13 h60
  text "DRILLING:" at 11332.46,3790.64 h60
  text "3x Internal routed cutouts" at 2705,3715 h60
  text "REFERENCE:" at 11407.23,3673.64 h60
  text "X" at 12055.46,3673.64 h60
  text "AS SHOWN" at 12242.46,3673.64 h60
  text "X" at 12956.46,3673.64 h60
  text "NC_DRILL FILES" at 13093.46,3673.64 h60
  text "Unplated" at 2710,3610 h60
  text "PTH MIN COPPER THICKNESS:" at 11407.23,3515.64 h60
  text "X" at 12757.46,3515.64 h60
  text "1MIL" at 12894.46,3515.64 h60
  text "OTHER" at 13391.46,3515.64 h60
  text "Gerber data in SV601229-A_PCB.gm18 file" at 2710,3505 h60
  text "BOARD FINISH:" at 11332.46,3356.64 h60
  text "SILKSCREEN:" at 11487.68,3238.64 h60
  text "X" at 12436.46,3238.64 h60
  text "TOP" at 12562.46,3238.64 h60
  text "X" at 12946.46,3238.64 h60
  text "BOTTOM" at 13073.46,3238.64 h60
  text "SILKSCREEN COLOR:" at 11487.68,3071.64 h60
  text "X" at 12435.42,3071.64 h60
  text "WHITE" at 12562.46,3071.64 h60
  text "OTHER" at 13073.46,3071.64 h60
  text "SOLDER RESIST COLOR:" at 11487.68,2901.64 h60
  text "X" at 12055.42,2742.44 h60
  text "GREEN" at 12182.46,2742.44 h60
  text "BLUE" at 12773.46,2742.44 h60
  text "OTHER" at 13311.46,2742.44 h60
  text "IMMERSION GOLD (ENIG)" at 12393.46,2553.92 h60
  text "ENEPIG" at 13731,2550.64 h60
  text "SURFACE FINISH:" at 11332.46,2549.64 h60
  text "X" at 12206.51,2549.64 h60
  text "IMM. TIN/SILVER OR EQUIV" at 11662,2392.64 h60
  text "OTHER" at 13093.46,2392.64 h60
  text "ARRAY/PANEL:" at 11332.46,2213.64 h60
  text "CUT AND TRIM PER MECH LAYER 1" at 12393.46,2209.35 h60
  text "X" at 12210,2065 h60
  text "N.C. ROUTE" at 12393.46,2057.64 h60
  text "V. SCORE" at 13259.46,2057.64 h60
  text "CERTIFICATION:" at 11332.46,1920.64 h60
  text "MATERIALS AND WORKMANSHIP FOR ALL PCBS" at 12057.46,1920.64 h60
  text "TO MEET OR EXCEED THE REQUIREMENTS OF:" at 12057.46,1822.64 h60
  text "X" at 11683.96,1686.13 h60
  text "ANSI IPC-A-600F CLASS ->" at 11822.96,1686.13 h60
  text "X" at 13462.02,1686.13 h60
  text "2" at 13580.96,1686.14 h60
  text "1" at 13265.96,1684.64 h60
  text "3" at 13934.96,1684.64 h60
  text "X" at 11686.02,1526.64 h60
  text "UL 94V-0" at 11822.96,1526.64 h60
  text "X" at 12498.02,1526.64 h60
  text "RoHS" at 12634.96,1526.64 h60
  text "OTHER" at 13279.36,1526.64 h60
  text "PER ORDER" at 13676.42,1526.64 h60
  text "ADDITIONAL REQUIREMENTS:" at 11332.46,1385.64 h60
  text "MICROSECTION:" at 11407.23,1270.64 h60
  text "YES" at 12312.96,1270.64 h60
  text "REQUIRED" at 13174.46,1114.49 h60
  text "BARE BOARD ELEC. TEST:" at 11407.23,1111.64 h60
  text "NONE" at 12712.96,1111.64 h60
  text "X" at 13047.46,1111.64 h60
  text "PER ORDER" at 13766.46,1111.64 h60
  text "MANUFACTURER'S UL:" at 11407.23,954.64 h60
  text "RAIL" at 12572.96,950.35 h60
  text "METAL" at 13064.77,950.35 h60
  text "X" at 13440,950 h60
  text "SILK" at 13576.46,950.35 h60
  text ".Layer_Name" at 577,-858.49 h60
M11 Gerber Information:
  lines w10: -292,-930.17 6308,-930.17 ; -292,-726.83 6310,-726.83 ; -292,-523.5 -292,-1133.5 3713,-1133.5 6310,-1133.5 6310,-523.5 -291.5,-523.5 -291.5,-1133.5 1284,-1133.5 ; 2173,-1133.5 2173,-523.5 ; 3440,-726.83 3440,-523.5 ; 4280,-726.83 4280,-523.5 ; 4902,-1140 4902,-937.17
  text "ALL ARTWORK VIEWED FROM TOP SIDE" at -228.5,-655.67 h60
  text "BOARD #:" at 2248,-655.67 h60
  text ".PRJ_Number" at 2793.5,-655.67 h60
  text "REV:" at 3638,-655.67 h60
  text ".PCB_Rev" at 3929.5,-655.67 h60
  text "SVN REV:" at 4476,-655.67 h60
  text ".VersionControl_RevNumber" at 4982,-655.67 h60
  text "LAYER NAME =" at -228.5,-858.49 h60
  text "PLOT NAME =" at -228.5,-1064.34 h60
  text ".plot_File_Name" at 577,-1064.34 h60
  text "GENERATED    :" at 2250,-1064.34 h60
  text ".Print_Date" at 3119.5,-1064.34 h60
  text ".Print_Time" at 3848.5,-1064.34 h60
  text "TEXAS INSTRUMENTS" at 5113,-1064.34 h60
M12 Stackup:
  lines w7: 11370,7679.25 14225,7679.25 ; 11370,7813.35 14225,7813.35 ; 11310,6108 ccw(c11353,6108) 11353,6065 14242,6065 ccw(c14242,6108) 14285,6108 14285,7917 ccw(c14242,7917) 14242,7960 11353,7960 ccw(c11353,7917) 11310,7917 11310,6108
  text "Layer Stack Up Detail for: LMG5200POLEVM-10.PcbDoc" at 11370,7845.38 h56
  text "Layer" at 11370,7763.35 h31
  text "Gerber" at 12378.43,7763.35 h31
  text "Copper" at 12974.26,7763.35 h31
  text "Dielectric" at 13620.71,7763.35 h31
  text "Name" at 11370,7701.35 h31
  text "Document" at 12378.43,7701.35 h31
  text "Thickness" at 12974.26,7701.35 h31
  text "Material" at 13620.71,7701.35 h31
  text "Top Solder Mask" at 11370,7614.56 h43
  text "(.GTS)" at 12378.43,7614.56 h43
  text "Solder Resist" at 13620.71,7614.56 h43
  text "Top Layer" at 11370,7492.17 h43
  text "(.GTL)" at 12378.43,7492.17 h43
  text "2.8mil" at 12974.26,7492.17 h43
  text "FR-4" at 13620.71,7430.98 h43
  text "MidLayer1" at 11370,7369.79 h43
  text "(.G1)" at 12378.43,7369.79 h43
  text "2.8mil" at 12974.26,7369.79 h43
  text "FR-4" at 13620.71,7308.59 h43
  text "MidLayer2" at 11370,7247.4 h43
  text "(.G2)" at 12378.43,7247.4 h43
  text "2.8mil" at 12974.26,7247.4 h43
  text "FR-4" at 13620.71,7186.21 h43
  text "MidLayer3" at 11370,7125.02 h43
  text "(.G3)" at 12378.43,7125.02 h43
  text "2.8mil" at 12974.26,7125.02 h43
  text "FR-4" at 13620.71,7063.82 h43
  text "MidLayer4" at 11370,7002.63 h43
  text "(.G4)" at 12378.43,7002.63 h43
  text "2.8mil" at 12974.26,7002.63 h43
  text "FR-4" at 13620.71,6941.44 h43
  text "MidLayer5" at 11370,6880.24 h43
  text "(.G5)" at 12378.43,6880.24 h43
  text "2.8mil" at 12974.26,6880.24 h43
  text "FR-4" at 13620.71,6819.05 h43
  text "MidLayer6" at 11370,6757.86 h43
  text "(.G6)" at 12378.43,6757.86 h43
  text "2.8mil" at 12974.26,6757.86 h43
  text "FR-4" at 13620.71,6696.67 h43
  text "MidLayer7" at 11370,6635.47 h43
  text "(.G7)" at 12378.43,6635.47 h43
  text "2.8mil" at 12974.26,6635.47 h43
  text "FR-4" at 13620.71,6574.28 h43
  text "MidLayer8" at 11370,6513.09 h43
  text "(.G8)" at 12378.43,6513.09 h43
  text "2.8mil" at 12974.26,6513.09 h43
  text "FR-4" at 13620.71,6451.9 h43
  text "Bottom Layer" at 11370,6390.7 h43
  text "(.GBL)" at 12378.43,6390.7 h43
  text "2.8mil" at 12974.26,6390.7 h43
  text "Bottom Solder Mask" at 11370,6268.32 h43
  text "(.GBS)" at 12378.43,6268.32 h43
  text "Solder Resist" at 13620.71,6268.32 h43
  text ".Layer_Name" at 577,-858.49 h60
M13 Component Bodies Top:
  text ".Layer_Name" at 577,-858.49 h60
M14 Component Bodies Bottom:
  text ".Layer_Name" at 577,-858.49 h60
M15 Courtyards Top:
  text ".Layer_Name" at 577,-858.49 h60
M16 Courtyards Bottom:
  text ".Layer_Name" at 577,-858.49 h60
Drill Drawing:
  text ".legend" at 6400,-450 h60
  text ".Layer_Name" at 577,-858.49 h60

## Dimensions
0,0 to 0,2375 on M2 Board Dimensions
0,0 to 3875,0 on M2 Board Dimensions
0,-410.5 to 1000,-410.5 on M2 Board Dimensions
